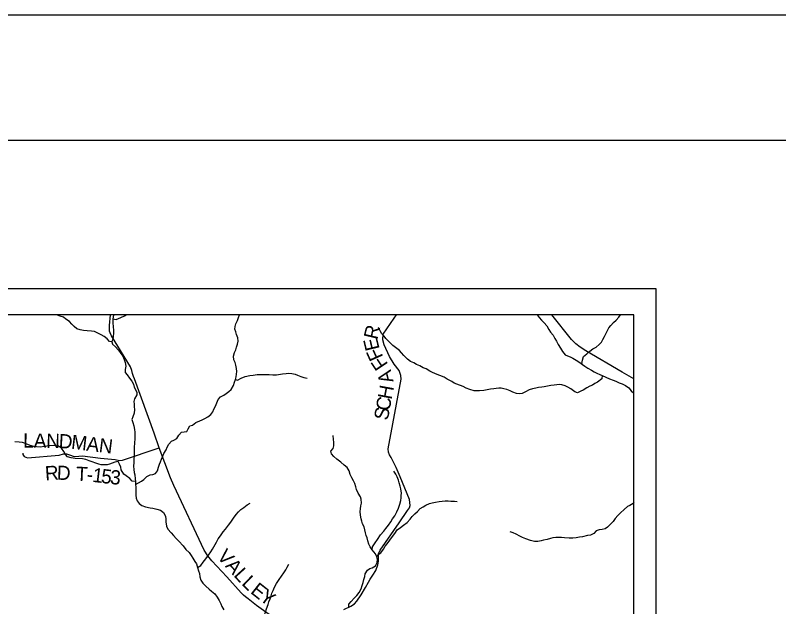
# Model space of a CAD drawing. Extents: x 0 to 34, y 0 to 22.
# Drawn here: x 6.52 to 9.58, y 19.631 to 22 of the extents above; entities that cross this region are included whole.
import ezdxf

# ---------------------------------------------------------------- set-up
doc = ezdxf.new("R2010")
doc.units = 0
for name, color, linetype in [('Default', 7, 'Continuous'), ('GM_X_County_Road', 7, 'Continuous'), ('GM_X_County_Road_Text', 7, 'Continuous'), ('GM_X_Minor_River', 7, 'Continuous'), ('GM_X_Township_Road', 7, 'Continuous'), ('GM_X_Township_Road_Text', 7, 'Continuous'), ('SH_Border', 7, 'Continuous'), ('SH_Cut_Line', 7, 'Continuous')]:
    doc.layers.add(name, color=color, linetype=linetype)

msp = doc.modelspace()

# ---------------------------------------------------------------- linework, layer by layer
at = {"layer": 'Default'}
for points in [[(9.087, 13.8822), (2.1062, 13.8822), (2.1062, 20.9054), (9.087, 20.9054)], [(9, 18.8941), (9, 20.8), (5.8621, 20.8), (5.6166, 20.2359), (5.6047, 20.2229), (5.5951, 20.2127), (5.5869, 20.1933), (5.5834, 20.1771), (5.5783, 20.1528), (5.5679, 20.1313), (5.5496, 20.1004), (5.1782, 19.2598), (5.1554, 19.2083), (5.3224, 19.1939), (5.8337, 19.1499), (6.226, 19.1161), (6.8442, 19.0679), (8.0305, 18.9725), (8.8762, 18.9027)]]:
    msp.add_lwpolyline(points, close=True, dxfattribs=at)
at = {"layer": 'GM_X_County_Road'}
for points in [[(7.556, 19.5857), (7.4872, 19.6361), (7.4528, 19.6619), (7.4423, 19.6708), (7.4341, 19.6767), (7.4255, 19.6859), (7.3684, 19.7497), (7.3082, 19.8143), (7.2911, 19.8341), (7.2772, 19.8567), (7.1554, 20.1166), (7.1416, 20.1472), (7.0962, 20.2674), (7.0766, 20.3258), (6.9972, 20.5435), (6.9933, 20.5534), (6.9897, 20.5649), (6.9873, 20.5771), (6.9811, 20.5913), (6.9059, 20.7162), (6.8997, 20.7273), (6.8972, 20.735), (6.8973, 20.757), (6.9019, 20.8)], [(9, 20.5429), (8.9532, 20.5709), (8.8074, 20.6555), (8.7837, 20.6698), (8.7668, 20.6837), (8.7492, 20.701), (8.6704, 20.8)]]:
    msp.add_lwpolyline(points, dxfattribs=at)
at = {"layer": 'GM_X_Minor_River'}
for points in [[(6.9071, 20.6924), (6.8976, 20.6937), (6.8883, 20.704), (6.8766, 20.7129), (6.8638, 20.7198), (6.851, 20.7264), (6.8377, 20.7326), (6.8253, 20.7346), (6.8086, 20.7352), (6.793, 20.7369), (6.7802, 20.7397), (6.7662, 20.7444), (6.756, 20.7528), (6.7467, 20.7628), (6.7377, 20.7727), (6.723, 20.7827), (6.7128, 20.7904), (6.6996, 20.7944), (6.6886, 20.7983), (6.6849, 20.8)], [(6.9135, 20.8), (6.9132, 20.7986), (6.9104, 20.7842), (6.9106, 20.7683), (6.9123, 20.7523), (6.9133, 20.739), (6.9132, 20.7261), (6.9119, 20.7136), (6.9103, 20.703), (6.9071, 20.6924), (6.9096, 20.6826), (6.9209, 20.6714), (6.9329, 20.6599), (6.94, 20.6492), (6.9505, 20.6343), (6.9564, 20.6214), (6.9597, 20.6088), (6.9625, 20.594), (6.9609, 20.5808), (6.9604, 20.5694), (6.9678, 20.5591), (6.9776, 20.5468), (6.9869, 20.5338), (6.9932, 20.5224), (6.9969, 20.5098), (7.0036, 20.4988), (7.0069, 20.4893), (7.0064, 20.479), (6.9975, 20.4632), (6.9955, 20.4526), (6.9958, 20.4427), (6.9968, 20.431), (6.9978, 20.4207), (6.9965, 20.4063), (6.9907, 20.3916), (6.9875, 20.381), (6.9908, 20.3688), (6.9948, 20.3548), (6.9973, 20.3411), (6.9987, 20.3297), (6.9997, 20.3168), (6.9995, 20.302), (6.9983, 20.2891), (6.9969, 20.2675), (6.9968, 20.2558), (6.9963, 20.2455), (6.9958, 20.2357), (6.9952, 20.2216), (6.9947, 20.2084), (6.9942, 20.1932), (6.9952, 20.1807), (6.9969, 20.1685), (6.9984, 20.159), (7.0001, 20.1431), (7.0015, 20.1321), (7.0021, 20.1203), (7.0027, 20.1097), (7.0034, 20.0983), (7.0033, 20.0881), (7.0035, 20.0778), (7.0049, 20.0661), (7.009, 20.0543), (7.0164, 20.0447), (7.027, 20.0366)], [(6.9104, 20.7842), (6.9236, 20.7818), (6.9339, 20.7855), (6.9434, 20.7892), (6.9572, 20.7955), (6.9648, 20.8)], [(7.0021, 20.1203), (7.0143, 20.1266), (7.0254, 20.133), (7.0353, 20.1405), (7.0468, 20.1525), (7.0606, 20.1588), (7.0712, 20.1598), (7.0819, 20.1646), (7.0896, 20.1755), (7.0939, 20.1903), (7.0982, 20.2012), (7.1017, 20.2114), (7.106, 20.2212), (7.1115, 20.2337), (7.1157, 20.2447), (7.1246, 20.259), (7.1282, 20.2699), (7.1347, 20.2824), (7.1455, 20.2936), (7.1558, 20.2977), (7.1672, 20.304), (7.175, 20.318), (7.1861, 20.33), (7.1963, 20.331), (7.2077, 20.3321), (7.2132, 20.343), (7.2194, 20.3554), (7.23, 20.358), (7.243, 20.3689), (7.259, 20.3759), (7.2693, 20.3792), (7.2796, 20.384), (7.2911, 20.3907), (7.3033, 20.4008), (7.3122, 20.4117), (7.3161, 20.4219), (7.3219, 20.4344), (7.3328, 20.4601), (7.3424, 20.4721), (7.3554, 20.4784), (7.3653, 20.4844), (7.3756, 20.493), (7.3856, 20.5012), (7.3941, 20.5163), (7.3984, 20.5303), (7.4023, 20.5409), (7.4047, 20.5511), (7.4064, 20.5625), (7.4076, 20.5727), (7.407, 20.5856), (7.4045, 20.5977), (7.4012, 20.6088), (7.3956, 20.6195), (7.3943, 20.6343), (7.399, 20.649), (7.4033, 20.6603), (7.4072, 20.6705), (7.4111, 20.683), (7.4128, 20.6951), (7.4114, 20.7077), (7.4066, 20.7217), (7.4041, 20.7316), (7.4004, 20.7427), (7.4013, 20.7536), (7.4044, 20.7639), (7.4106, 20.7778), (7.4146, 20.7899), (7.4183, 20.8)], [(8.6116, 20.8), (8.62, 20.7891), (8.6294, 20.7792), (8.6395, 20.7684), (8.65, 20.7554), (8.6586, 20.7417), (8.6657, 20.7302), (8.6758, 20.718), (8.6832, 20.7054), (8.6888, 20.6951), (8.6962, 20.6806), (8.7048, 20.6669), (8.7134, 20.6535), (8.7239, 20.6398), (8.734, 20.6355), (8.7439, 20.6312), (8.7544, 20.6258), (8.7684, 20.6184), (8.7827, 20.6088), (8.7936, 20.6011), (8.8034, 20.5946), (8.8155, 20.5869), (8.8298, 20.5784), (8.8403, 20.5722), (8.8509, 20.5668), (8.863, 20.5613), (8.8728, 20.5571), (8.8867, 20.5501), (8.9015, 20.5442), (8.9162, 20.538), (8.9268, 20.5341), (8.9407, 20.5279), (8.9521, 20.5236), (8.9664, 20.517), (8.9788, 20.5078), (8.9893, 20.4959), (9, 20.4866)], [(8.7936, 20.6011), (8.7906, 20.6049), (8.7934, 20.6189), (8.7981, 20.6325), (8.8108, 20.6438), (8.8226, 20.6539), (8.8353, 20.6633), (8.8482, 20.6707), (8.8609, 20.6812), (8.8697, 20.691), (8.8751, 20.7015), (8.8817, 20.7125), (8.889, 20.726), (8.8933, 20.7366), (8.8988, 20.7472), (8.9076, 20.7569), (8.918, 20.7686), (8.9279, 20.7787), (8.9387, 20.79), (8.9461, 20.8)], [(8.8728, 20.5571), (8.8711, 20.5438), (8.8535, 20.53), (8.8432, 20.5244), (8.8337, 20.5188), (8.8234, 20.514), (8.8112, 20.5073), (8.7963, 20.4987), (8.7867, 20.4935), (8.7734, 20.4876), (8.7632, 20.4911), (8.7466, 20.503), (8.7342, 20.51), (8.724, 20.515), (8.7111, 20.5189), (8.7009, 20.5202), (8.6903, 20.5199), (8.6797, 20.5185), (8.666, 20.5167), (8.6531, 20.5146), (8.6401, 20.5121), (8.6306, 20.5106), (8.6166, 20.5085), (8.6059, 20.506), (8.5926, 20.5038), (8.5801, 20.499), (8.5652, 20.4908), (8.5515, 20.4849), (8.5397, 20.4831), (8.5287, 20.4848), (8.5143, 20.4902), (8.503, 20.4957), (8.4909, 20.5011), (8.4781, 20.5039), (8.4675, 20.5055), (8.4576, 20.5056), (8.4477, 20.505), (8.4382, 20.5035), (8.4249, 20.5018), (8.412, 20.4993), (8.3983, 20.4971), (8.3801, 20.4954), (8.3695, 20.4952), (8.3593, 20.4956), (8.3422, 20.5007), (8.3271, 20.5062), (8.3147, 20.5128), (8.2897, 20.5221), (8.2796, 20.5264), (8.2694, 20.5334), (8.2513, 20.5423), (8.2392, 20.55), (8.2215, 20.557), (8.2109, 20.5605), (8.1924, 20.5683), (8.1822, 20.5741), (8.1668, 20.5833), (8.1547, 20.588), (8.1419, 20.595), (8.1286, 20.6004), (8.1173, 20.6077), (8.1041, 20.6132), (8.0921, 20.6217), (8.0775, 20.6374), (8.0685, 20.6473), (8.0595, 20.6569), (8.044, 20.6688), (8.0331, 20.6773), (8.02, 20.6903), (8.0057, 20.7045), (7.9979, 20.714), (7.9896, 20.7244), (7.9826, 20.7354), (7.9763, 20.7488)], [(7.4023, 20.5409), (7.4103, 20.5385), (7.4248, 20.546), (7.4419, 20.5534), (7.4606, 20.557), (7.4735, 20.5583), (7.4894, 20.5612), (7.5069, 20.5614), (7.5277, 20.5612), (7.5372, 20.5607), (7.5528, 20.5594), (7.5664, 20.5593), (7.5911, 20.5639), (7.6055, 20.5653), (7.6154, 20.5656), (7.6279, 20.5647), (7.6412, 20.5619), (7.6517, 20.558), (7.6642, 20.5529), (7.6763, 20.5483), (7.6899, 20.5458)], [(7.0015, 20.1321), (6.9882, 20.1337), (6.9785, 20.1441), (6.9649, 20.1552), (6.9551, 20.1622), (6.9447, 20.1789), (6.9425, 20.1892), (6.9381, 20.2021), (6.9318, 20.2125), (6.9185, 20.2099), (6.9082, 20.2051), (6.8975, 20.2018), (6.8877, 20.1996), (6.8751, 20.1994), (6.8645, 20.1995), (6.8547, 20.2011), (6.8422, 20.2058), (6.8278, 20.2105), (6.8165, 20.2156), (6.8022, 20.2206), (6.7889, 20.2234), (6.7605, 20.2249), (6.7438, 20.2266), (6.7291, 20.2305), (6.7208, 20.2401), (6.7141, 20.2523), (6.7052, 20.266), (6.6924, 20.2734), (6.6742, 20.2766), (6.6567, 20.2745), (6.6465, 20.2738), (6.6362, 20.2724), (6.6206, 20.2703), (6.6051, 20.2705), (6.5937, 20.2725), (6.579, 20.2764), (6.5628, 20.2838), (6.5488, 20.2889), (6.5359, 20.2898), (6.5185, 20.2911)], [(7.8574, 19.6257), (7.8572, 19.6405), (7.8656, 19.6517), (7.8783, 19.6645), (7.8894, 19.675), (7.8983, 19.6882), (7.906, 19.7029), (7.9099, 19.715), (7.9142, 19.7274), (7.9174, 19.7392), (7.921, 19.7516), (7.923, 19.7626), (7.9315, 19.7766), (7.941, 19.7833), (7.9506, 19.787), (7.9635, 19.7948), (7.9705, 19.8084), (7.9718, 19.8197), (7.9696, 19.83), (7.9633, 19.8422), (7.9506, 19.8579), (7.9427, 19.8709), (7.9376, 19.8815), (7.9331, 19.8945), (7.9299, 19.9063), (7.9269, 19.9158), (7.924, 19.926), (7.9207, 19.939), (7.9182, 19.9507), (7.9123, 19.9633), (7.9086, 19.9732), (7.9064, 19.9827), (7.9032, 19.9968), (7.9026, 20.0116), (7.9031, 20.0222), (7.9055, 20.0354), (7.9075, 20.046), (7.9069, 20.0612), (7.9036, 20.0707), (7.8946, 20.0852), (7.8876, 20.0997), (7.8854, 20.1111), (7.881, 20.1248), (7.8762, 20.1347), (7.8691, 20.1465), (7.8621, 20.1607), (7.8588, 20.1755), (7.8502, 20.1877), (7.8382, 20.1977), (7.8247, 20.2092), (7.8093, 20.2215), (7.7969, 20.2319), (7.7871, 20.2426), (7.7842, 20.2544), (7.7938, 20.2649), (7.797, 20.2755), (7.7964, 20.2899), (7.795, 20.3005), (7.7936, 20.3165)], [(7.9506, 19.8579), (7.9522, 19.8711), (7.9619, 19.887), (7.9723, 19.8994), (7.9842, 19.9182), (7.9969, 19.9329), (8.0054, 19.9442), (8.0158, 19.9573), (8.0254, 19.9712), (8.0323, 19.9822), (8.0416, 19.9953), (8.0497, 20.0104), (8.0563, 20.0251), (8.0614, 20.0414), (8.065, 20.0565), (8.0663, 20.0664), (8.0671, 20.0758), (8.0676, 20.0853), (8.0655, 20.1032), (8.063, 20.1138), (8.059, 20.1271), (8.0561, 20.1382), (8.0505, 20.1511), (8.0453, 20.161), (8.0367, 20.1736)], [(7.2507, 19.7882), (7.2633, 19.796), (7.2726, 19.8092), (7.2833, 19.8231), (7.2949, 19.8374), (7.3034, 19.8506), (7.3099, 19.8612), (7.3269, 19.889), (7.3331, 19.9019), (7.3424, 19.915), (7.3536, 19.9308), (7.362, 19.9418), (7.3747, 19.9572), (7.3836, 19.9688), (7.3947, 19.985), (7.4048, 19.9997), (7.4147, 20.011), (7.4243, 20.02), (7.4358, 20.0286), (7.4492, 20.0387), (7.4614, 20.0461)], [(7.9696, 19.83), (7.9735, 19.8379), (7.9846, 19.8462), (7.9954, 19.8608), (8.0031, 19.8733), (8.0104, 19.8831), (8.0212, 19.897), (8.0316, 19.912), (8.0412, 19.9244), (8.0512, 19.9384), (8.0635, 19.9485), (8.0764, 19.9567), (8.0914, 19.9683), (8.1025, 19.9811), (8.111, 19.992), (8.1213, 20.0025), (8.1317, 20.0119), (8.1432, 20.0239), (8.155, 20.0313), (8.1653, 20.0369), (8.1798, 20.0436), (8.1908, 20.0465), (8.2045, 20.0498), (8.219, 20.0527), (8.2304, 20.0541), (8.2429, 20.0547), (8.2554, 20.0542), (8.266, 20.0533), (8.2804, 20.0532), (8.2907, 20.0523)], [(9, 20.048), (8.9961, 20.0446), (8.9832, 20.0364), (8.9736, 20.0316), (8.961, 20.0199), (8.9464, 20.0072), (8.9357, 19.9955), (8.9249, 19.9835), (8.9168, 19.9715), (8.9065, 19.9613), (8.8942, 19.9497), (8.8843, 19.943), (8.8721, 19.9405), (8.8599, 19.9383), (8.8485, 19.935), (8.8389, 19.9234), (8.8252, 19.9171), (8.8138, 19.916), (8.7936, 19.9106), (8.7811, 19.9088), (8.7686, 19.9067), (8.7545, 19.9057), (8.7408, 19.9054), (8.7215, 19.9064), (8.7098, 19.9073), (8.6984, 19.9078), (8.687, 19.9075), (8.6752, 19.9061), (8.6653, 19.9039), (8.652, 19.9003), (8.6376, 19.8966), (8.6277, 19.8941), (8.6148, 19.8923), (8.6007, 19.8925), (8.5845, 19.8957), (8.5659, 19.9019), (8.5535, 19.9085), (8.5418, 19.9139), (8.5271, 19.9209), (8.5158, 19.9263), (8.5037, 19.931)], [(7.027, 20.0366), (7.0421, 20.0312), (7.061, 20.0264), (7.0709, 20.0248), (7.0875, 20.022), (7.1015, 20.018), (7.1143, 20.0077), (7.1217, 19.9939), (7.1231, 19.9814), (7.1234, 19.9712), (7.1262, 19.9533), (7.1318, 19.9411), (7.1449, 19.9266), (7.1542, 19.9155), (7.1647, 19.9036), (7.1752, 19.8933), (7.1925, 19.8745), (7.2041, 19.8604), (7.2165, 19.8477), (7.2251, 19.8355), (7.2314, 19.8248), (7.24, 19.8122), (7.2456, 19.8019), (7.2507, 19.7882), (7.2547, 19.7741), (7.2577, 19.7635), (7.2602, 19.7502), (7.2631, 19.7373), (7.2717, 19.7254), (7.284, 19.7135), (7.2964, 19.7009), (7.307, 19.6932), (7.3194, 19.6825), (7.3294, 19.6683), (7.3373, 19.6561), (7.3432, 19.6428), (7.3473, 19.6321), (7.3554, 19.618)], [(7.4445, 19.5064), (7.4541, 19.5146), (7.4675, 19.5251), (7.4836, 19.5393), (7.4955, 19.5544), (7.5063, 19.569), (7.514, 19.5856), (7.5187, 19.5985), (7.5226, 19.6094), (7.5269, 19.6215), (7.5332, 19.6389), (7.5367, 19.6506), (7.541, 19.6619), (7.545, 19.6744), (7.5485, 19.6854), (7.5532, 19.6956), (7.5586, 19.7088), (7.5667, 19.7235), (7.5779, 19.7397), (7.5875, 19.7528), (7.5964, 19.7664), (7.6038, 19.7788), (7.6099, 19.7894), (7.6161, 19.8015)]]:
    msp.add_lwpolyline(points, dxfattribs=at)
at = {"layer": 'GM_X_Township_Road'}
for points in [[(7.8362, 19.6192), (7.8653, 19.6327), (7.8792, 19.6423), (7.8889, 19.6535), (7.9065, 19.6778), (7.9238, 19.7078), (7.936, 19.7284), (7.942, 19.7404), (7.9537, 19.7569), (7.9651, 19.7752), (7.9732, 19.7982), (7.9754, 19.8133), (7.9753, 19.8274), (7.9756, 19.8425), (7.9831, 19.8576), (8.0591, 19.9672), (8.0927, 20.0162), (8.1006, 20.0271), (8.103, 20.0365), (8.0997, 20.0605), (8.0813, 20.1056), (8.0625, 20.1515), (8.0473, 20.1879), (8.0262, 20.2278), (8.02, 20.2397), (8.0164, 20.25), (8.0151, 20.2625), (8.0661, 20.5423), (8.0653, 20.5571), (8.0581, 20.577), (8.0385, 20.6028), (8.0202, 20.6324), (7.9984, 20.6799), (7.9931, 20.6993), (7.9951, 20.7221), (8.0386, 20.7872), (8.0475, 20.8)], [(6.5502, 20.2463), (6.5504, 20.2399), (6.5556, 20.2326), (6.5688, 20.2277), (6.6958, 20.2377), (6.7133, 20.2434), (6.7255, 20.2435), (6.7375, 20.2391), (6.756, 20.233), (6.7739, 20.2342), (6.7899, 20.235), (6.8618, 20.2263), (6.9201, 20.2198), (6.9379, 20.2168), (6.9493, 20.2181), (7.0962, 20.2674)]]:
    msp.add_lwpolyline(points, dxfattribs=at)
at = {"layer": 'SH_Border'}
msp.add_lwpolyline([(1.5, 21.5), (33.5, 21.5), (33.5, 0.5), (1.5, 0.5)], close=True, dxfattribs=at)
at = {"layer": 'SH_Cut_Line'}
for points in [[(0, 0), (34, 0), (34, 22), (0, 22)], [(9, 18.8941), (9, 20.8), (2.2, 20.8), (2.2, 19.4329), (2.7961, 19.3885), (3.1893, 19.3592), (4.7641, 19.2419), (4.831, 19.2363), (5.1554, 19.2083), (5.3224, 19.1939), (5.8337, 19.1499), (6.226, 19.1161), (6.8442, 19.0679), (8.0305, 18.9725), (8.8762, 18.9027)]]:
    msp.add_lwpolyline(points, close=True, dxfattribs=at)

# ---------------------------------------------------------------- texts
at = {"layer": 'GM_X_County_Road_Text'}
for s, rotation, p in [('V', 312.0997, (7.3256, 19.8297)), ('A', 312.0958, (7.3592, 19.7926)), ('L', 312.2908, (7.3928, 19.7553)), ('L', 315.9773, (7.4242, 19.721)), ('E', 321.6811, (7.4594, 19.6874)), ('Y', 323.6743, (7.4945, 19.6598))]:
    msp.add_text(s, height=0.0568, rotation=rotation, dxfattribs=at).set_placement(p)
at = {"layer": 'GM_X_Township_Road_Text'}
for s, rotation, p in [('R', 76.7206, (7.9709, 20.6981)), ('E', 103.5748, (7.9808, 20.6637)), ('F', 114.361, (7.9957, 20.6315)), ('F', 124.0322, (8.0159, 20.6019)), ('A', 103.6989, (8.0366, 20.5333)), ('H', 79.5626, (8.0283, 20.4582)), ('C', 79.5494, (8.0198, 20.4123)), ('S', 79.546, (8.0129, 20.3746)), ('L', 359.1814, (6.551, 20.2685)), ('A', 359.1826, (6.5935, 20.2679)), ('N', 359.0328, (6.6435, 20.2672)), ('D', 356.7216, (6.6929, 20.2664)), ('M', 353.3839, (6.7419, 20.2636)), ('A', 352.8289, (6.803, 20.2565)), ('N', 352.8357, (6.8526, 20.2503)), ('R', 3.9705, (6.6407, 20.1364)), ('D', 357.7519, (6.6856, 20.1396)), ('T', 357.477, (6.7624, 20.1353)), ('1', 353.3107, (6.827, 20.131)), ('5', 353.3416, (6.8618, 20.1269)), ('3', 354.6697, (6.898, 20.1227)), ('-', 353.7939, (6.8039, 20.1335))]:
    msp.add_text(s, height=0.0568, rotation=rotation, dxfattribs=at).set_placement(p)

doc.saveas('drawing.dxf')
